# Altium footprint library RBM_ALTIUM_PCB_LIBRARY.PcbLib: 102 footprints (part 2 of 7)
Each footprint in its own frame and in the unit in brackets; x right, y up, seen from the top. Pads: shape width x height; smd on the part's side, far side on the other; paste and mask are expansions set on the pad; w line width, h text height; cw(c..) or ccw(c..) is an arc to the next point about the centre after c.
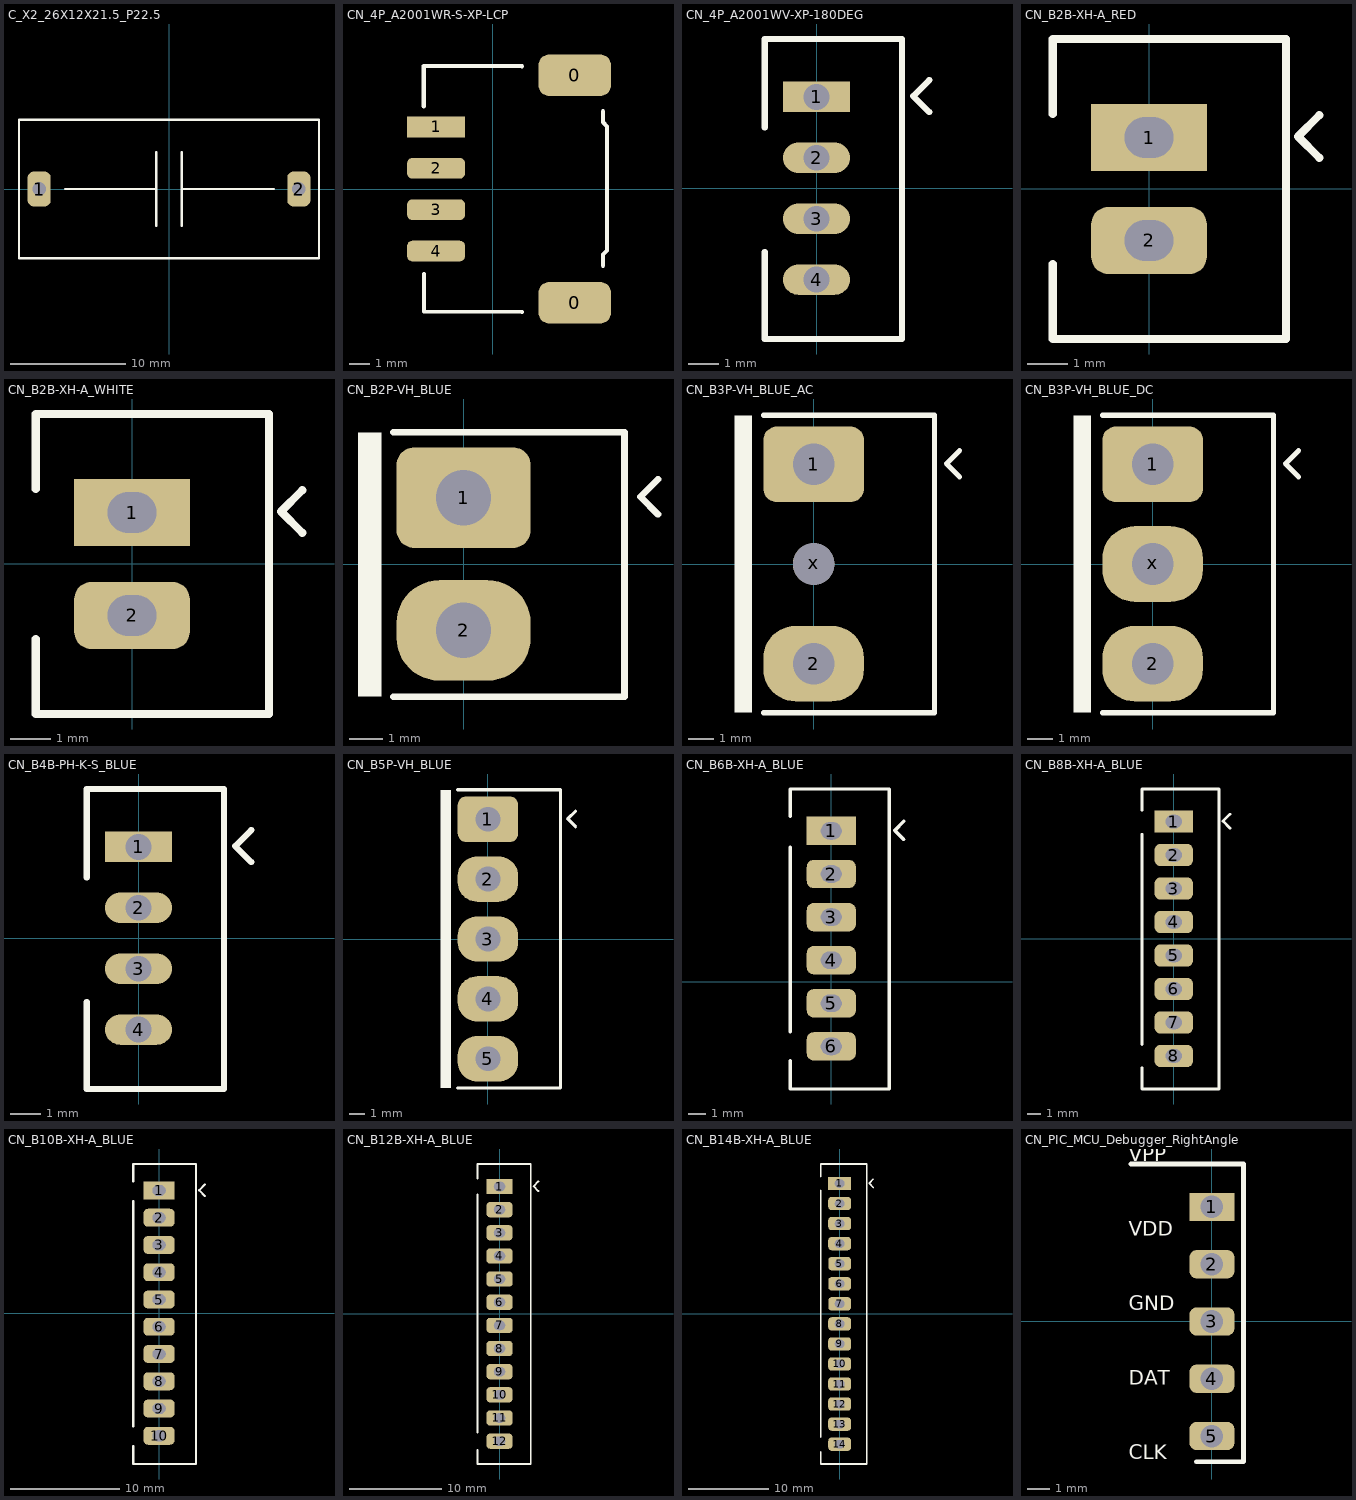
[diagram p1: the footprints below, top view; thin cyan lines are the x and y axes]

## C_X2_26X12X21.5_P22.5 [mm]
pads (2):
  rrect50% 2x3 hole 1.2: 1(-11.25,0) 2(11.25,0)
Top Overlay:
  lines w0.2: -9,0 -1.1,0 ; -1.1,-3.2 -1.1,3.2 ; 1.1,-3.2 1.1,3.2 ; 1.1,0 9.1,0 ; -13,-6 -13,6 13,6 13,-6 -13,-6
3D body: height 3, standoff -2, extent 10.852,-0.399 11.648,0.399
3D body: height 3, standoff -2, extent -11.648,-0.399 -10.852,0.399
3D body: height 21.5, standoff 0.2, extent -13,-6 13,6

## CN_4P_A2001WR-S-XP-LCP [mm]
pads (7):
  rrect50% 3.5x2 smd: 0(3.95,-5.5) 0(3.95,5.5)
  rect 2.8x1 smd: 1(-2.75,3)
  rrect50% 2.8x1 smd: 2(-2.75,1) 3(-2.75,-1) 4(-2.75,-3)
  round 0.5 on Top Overlay: ""(-4,4.6)
Top Overlay:
  lines w0.2: -3.35,4 -3.35,5.95 1.4,5.93 ; -3.334,-4.1 -3.334,-5.925 1.4,-5.945 ; 5.319,-3.712 5.319,-3.17 5.515,-2.974 5.515,3.029 5.319,3.225 5.319,3.76
3D body "S4B-PH-SM4-TB.STEP": height 5.6, standoff 0, extent -3.35,-5.95 5.25,5.95

## CN_4P_A2001WV-XP-180DEG [mm] "Top Entry Header 1.25mm pitch 1X4pin  180° long"
pads (4):
  rect 2.2x1 hole 0.85: 1(0,3)
  oval 2.2x1 hole 0.85: 2(0,1) 3(0,-1) 4(0,-3)
Top Overlay:
  lines w0.2: -1.7,-2.1 -1.7,-4.95 2.8,-4.95 2.8,4.9 -1.7,4.9 -1.7,2 ; 3.7,2.5 3.175,3.025 3.7,3.55
3D body "B4B-PH-K-S.STEP": height 6, standoff -3.4, extent -1.7,-4.95 2.8,4.95

## CN_B2B-XH-A_RED [mm]
pads (2):
  rect 2.85x1.65 hole 1.2 slot 1 at 90 deg: 1(0,1.27)
  rrect50% 2.85x1.65 hole 1.2 slot 1 at 90 deg: 2(0,-1.27)
Top Overlay:
  lines w0.2: -2.375,-1.85 -2.375,-3.7 3.375,-3.7 3.375,3.7 -2.375,3.7 -2.375,1.85 ; 4.2,0.77 3.675,1.295 4.2,1.82
3D body: height 7, standoff -3.5, extent -0.35,0.925 0.35,1.615
3D body: height 7, standoff -3.5, extent -0.35,-1.615 0.35,-0.925
3D body "B2B-XH-A.STEP": height 7, standoff -3.4, extent -2.375,-3.7 3.375,3.7

## CN_B2B-XH-A_WHITE [mm]
pads (2):
  rect 2.85x1.65 hole 1.2 slot 1 at 90 deg: 1(0,1.27)
  rrect50% 2.85x1.65 hole 1.2 slot 1 at 90 deg: 2(0,-1.27)
Top Overlay:
  lines w0.2: -2.375,-1.85 -2.375,-3.7 3.375,-3.7 3.375,3.7 -2.375,3.7 -2.375,1.85 ; 4.2,0.77 3.675,1.295 4.2,1.82
3D body "B2B-XH-A.STEP": height 7, standoff -3.4, extent -2.375,-3.7 3.375,3.7
3D body: height 7, standoff -3.5, extent -0.35,-1.615 0.35,-0.925
3D body: height 7, standoff -3.5, extent -0.35,0.925 0.35,1.615

## CN_B2P-VH_BLUE [mm] "3.96mm Pitch"
pads (2):
  rrect35% 4x3 hole 1.65: 1(0,1.98)
  rrect85% 4x3 hole 1.65: 2(0,-1.98)
Top Overlay:
  rectangle: -3.15,-3.96 -2.45,3.93
  lines w0.2: -2.1,-3.96 4.8,-3.96 4.8,3.93 -2.1,3.93 ; 5.8,1.48 5.275,2.005 5.8,2.53
3D body "B2P-VH.STEP": height 10.9, standoff -3.7, extent -3.75,-3.96 4.75,3.9

## CN_B3P-VH_BLUE_AC [mm] "3.96mm Pitch"
pads (3):
  rrect35% 4x3 / inner rect 4x2 / far side rect 4x2 hole 1.65: 1(0,3.96)
  rrect85% 4x3 hole 1.65: 2(0,-3.96)
  round 1.65 hole 1.65 unplated: x(0,0)
Top Overlay:
  rectangle: -3.15,-5.91 -2.45,5.91
  lines w0.2: -2,-5.91 4.8,-5.91 4.8,5.91 -2,5.91 ; 5.8,3.46 5.275,3.985 5.8,4.51
3D body "B3P-VH.STEP": height 10.9, standoff -3.7, extent -3.7,-5.91 4.8,5.91

## CN_B3P-VH_BLUE_DC [mm] "3.96mm Pitch"
pads (3):
  rrect35% 4x3 / inner rect 4x2 / far side rect 4x2 hole 1.65: 1(0,3.96)
  rrect85% 4x3 hole 1.65: 2(0,-3.96) x(0,0)
Top Overlay:
  rectangle: -3.15,-5.91 -2.45,5.91
  lines w0.2: -2,-5.91 4.8,-5.91 4.8,5.91 -2,5.91 ; 5.8,3.46 5.275,3.985 5.8,4.51
3D body "B3P-VH.STEP": height 10.9, standoff -3.7, extent -3.7,-5.91 4.8,5.91

## CN_B4B-PH-K-S_BLUE [mm] "Top Entry Header 2mm pitch 1X4pin  180° long"
pads (4):
  rect 2.2x1 hole 0.85: 1(0,3)
  oval 2.2x1 hole 0.85: 2(0,1) 3(0,-1) 4(0,-3)
Top Overlay:
  lines w0.2: -1.7,-2.1 -1.7,-4.95 2.8,-4.95 2.8,4.9 -1.7,4.9 -1.7,2 ; 3.7,2.5 3.175,3.025 3.7,3.55
3D body "B4B-PH-K-S.STEP": height 6, standoff -3.4, extent -1.7,-5 2.8,4.9

## CN_B5P-VH_BLUE [mm] "3.96mm Pitch"
pads (5):
  rrect35% 4x3 hole 1.65: 1(0,7.92)
  rrect85% 4x3 hole 1.65: 2(0,3.96) 3(0,0) 4(0,-3.96) 5(0,-7.92)
Top Overlay:
  rectangle: -3.15,-9.85 -2.45,9.87
  lines w0.2: -2,-9.85 4.8,-9.85 4.8,9.87 -2,9.87 ; 5.8,7.42 5.275,7.945 5.8,8.47
3D body "B5P-VH.STEP": height 10.9, standoff -3.7, extent -3.65,-9.85 4.85,9.89

## CN_B6B-XH-A_BLUE [mm] "2.5mm Pitch, 8pins, Top-Entry, XH Connector"
pads (6):
  rect 2.85x1.65 hole 1.2 slot 1 at 90 deg: 1(0,8.75)
  rrect50% 2.85x1.65 hole 1.2 slot 1 at 90 deg: 2(0,6.25) 3(0,3.75) 4(0,1.25) 5(0,-1.25) 6(0,-3.75)
Top Overlay:
  lines w0.2: -2.375,-6.22 3.375,-6.22 3.375,11.18 -2.375,11.18 -2.375,9.6 ; -2.375,-6.15 -2.375,-4.57 ; -2.375,-2.9 -2.375,7.8 ; 4.2,8.25 3.675,8.775 4.2,9.3
3D body "B6B-XH-A.STEP": height 7, standoff -3.4, extent -2.375,-6.22 3.375,11.18

## CN_B8B-XH-A_BLUE [mm] "2.5mm Pitch, 8pins, Top-Entry, XH Connector"
pads (8):
  rect 2.85x1.65 hole 1.2 slot 1 at 90 deg: 1(0,8.75)
  rrect50% 2.85x1.65 hole 1.2 slot 1 at 90 deg: 2(0,6.25) 3(0,3.75) 4(0,1.25) 5(0,-1.25) 6(0,-3.75) 7(0,-6.25) 8(0,-8.75)
Top Overlay:
  lines w0.2: -2.375,-9.64 -2.375,-11.22 3.375,-11.22 3.375,11.18 -2.375,11.18 -2.375,9.6 ; -2.375,-7.9 -2.375,7.8 ; 4.2,8.25 3.675,8.775 4.2,9.3
3D body "B8B-XH-A.STEP": height 7, standoff -3.4, extent -2.375,-11.22 3.375,11.18

## CN_B10B-XH-A_BLUE [mm] "2.5mmPitch, TopEntry, BlueColor, XH Connector"
pads (10):
  rect 2.85x1.65 hole 1.2 slot 1 at 90 deg: 1(0,11.25)
  rrect50% 2.85x1.65 hole 1.2 slot 1 at 90 deg: 2(0,8.75) 3(0,6.25) 4(0,3.75) 5(0,1.25) 6(0,-1.25) 7(0,-3.75) 8(0,-6.25) 9(0,-8.75) 10(0,-11.25)
Top Overlay:
  lines w0.2: -2.375,-12.2 -2.375,-13.84 3.375,-13.84 3.375,13.68 -2.375,13.68 -2.375,12.1 ; -2.375,-10.4 -2.375,10.3 ; 4.2,10.75 3.675,11.275 4.2,11.8
3D body "B10B-XH-A.STEP": height 7, standoff -3.4, extent -2.375,-13.72 3.375,13.68

## CN_B12B-XH-A_BLUE [mm] "2.5mmPitch, TopEntry, BlueColor, XH Connector"
pads (12):
  rect 2.85x1.65 hole 1.2 slot 1 at 90 deg: 1(0,13.75)
  rrect50% 2.85x1.65 hole 1.2 slot 1 at 90 deg: 2(0,11.25) 3(0,8.75) 4(0,6.25) 5(0,3.75) 6(0,1.25) 7(0,-1.25) 8(0,-3.75) 9(0,-6.25) 10(0,-8.75) 11(0,-11.25) 12(0,-13.75)
Top Overlay:
  lines w0.2: -2.375,-14.7 -2.375,-16.22 3.375,-16.22 3.375,16.18 -2.375,16.18 -2.375,14.6 ; -2.375,-12.8 -2.375,12.9 ; 4.2,13.25 3.675,13.775 4.2,14.3
3D body "B12B-XH-A.STEP": height 7, standoff -3.4, extent -2.375,-16.22 3.375,16.18

## CN_B14B-XH-A_BLUE [mm] "2.5mmPitch, TopEntry, BlueColor, XH Connector"
pads (14):
  rect 2.85x1.65 hole 1.2 slot 1 at 90 deg: 1(0,16.25)
  rrect50% 2.85x1.65 hole 1.2 slot 1 at 90 deg: 2(0,13.75) 3(0,11.25) 4(0,8.75) 5(0,6.25) 6(0,3.75) 7(0,1.25) 8(0,-1.25) 9(0,-3.75) 10(0,-6.25) 11(0,-8.75) 12(0,-11.25) 13(0,-13.75) 14(0,-16.25)
Top Overlay:
  lines w0.2: -2.375,-17.2 -2.375,-18.72 3.375,-18.72 3.375,18.68 -2.375,18.68 -2.375,17.1 ; -2.375,-15.4 -2.375,15.4 ; 4.2,15.75 3.675,16.275 4.2,16.8
3D body "B14B-XH-A.STEP": height 7, standoff -3.4, extent -2.375,-18.72 3.375,18.68

## CN_PIC_MCU_Debugger_RightAngle [mm] "2.54mmPitch, 5pins, StraightType, Male Connector"
pads (5):
  rect 2x1.25 hole 1: 1(0,5.08)
  rrect50% 2x1.25 hole 1: 2(0,2.54) 3(0,0) 4(0,-2.54) 5(0,-5.08)
Top Overlay:
  lines w0.203: -3.6,6.985 1.4,6.985 1.4,-6.22 -0.7,-6.22
  text "VPP /  /  / VDD /  /  / GND /  /  / DAT /  /  / CLK" at -3.7,-6.32 h1.1
Bottom Overlay:
  lines w0.203: -3.6,6.98 1.4,6.98 1.4,-6.225 -0.7,-6.225
  text "VPP /  /  / VDD /  /  / GND /  /  / DAT /  /  / CLK" at -1.3,-6.32 h1.1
